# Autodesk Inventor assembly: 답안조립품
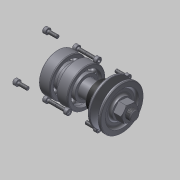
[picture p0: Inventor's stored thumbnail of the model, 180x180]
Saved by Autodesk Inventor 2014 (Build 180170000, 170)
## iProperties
Created: 2015-03
Part Number: 답안조립품
Document SubType Name: Assembly
Designer: MYHOME
Author: MYHOME
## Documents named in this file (11)
- C:\Documents and Settings\MYHOME\바탕 화면\450306V1012\답안조립품.iam
- C:\Documents and Settings\MYHOME\바탕 화면\450306V1012\본체.ipt
- C:\Documents and Settings\MYHOME\바탕 화면\450306V1012\커버.ipt
- C:\Documents and Settings\MYHOME\바탕 화면\450306V1012\커버2.ipt
- C:\Documents and Settings\MYHOME\바탕 화면\450306V1012\축.ipt
- C:\Documents and Settings\MYHOME\바탕 화면\450306V1012\베어링 6204.ipt
- C:\Documents and Settings\MYHOME\바탕 화면\450306V1012\오일실.ipt
- C:\Documents and Settings\MYHOME\바탕 화면\450306V1012\V벨트풀리.ipt
- C:\Documents and Settings\MYHOME\바탕 화면\450306V1012\키(4 x 4 x 12).ipt
- C:\Documents and Settings\MYHOME\바탕 화면\450306V1012\M 4 x 12.ipt
- C:\Documents and Settings\MYHOME\바탕 화면\450306V1012\너트 M12x1.25.ipt
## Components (14 placed, 6 different names)
1. KS B 2023 6204 - 20 x 47 x 14:1 — 각도:1
2. KS B 2023 6204 - 20 x 47 x 14:2 — 각도:2
3. KS B 2804 D D - 20 32 8:1
4. 그루브 풀리1:1
5. KS B 1311 (I) 4 x 4 x 12:1
6. KS B 1012 클래스 1 일반 - 미터 M12x1.25:1
7. KS B 1003 - 미터 M 4 x 12:1
8. KS B 1003 - 미터 M 4 x 12:3
9. KS B 1003 - 미터 M 4 x 12:4
10. KS B 1003 - 미터 M 4 x 12:5
11. KS B 1003 - 미터 M 4 x 12:2
12. KS B 1003 - 미터 M 4 x 12:6
13. KS B 1003 - 미터 M 4 x 12:7
14. KS B 1003 - 미터 M 4 x 12:8
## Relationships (2: Angle 2)
- 각도:1 [Angle]: KS B 2023 6204 - 20 x 47 x 14:1
- 각도:2 [Angle]: KS B 2023 6204 - 20 x 47 x 14:2
